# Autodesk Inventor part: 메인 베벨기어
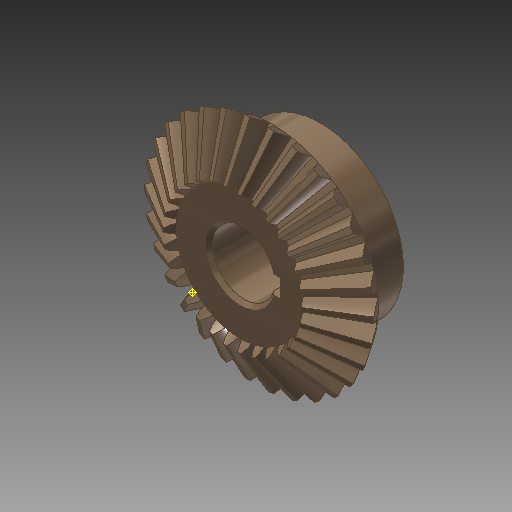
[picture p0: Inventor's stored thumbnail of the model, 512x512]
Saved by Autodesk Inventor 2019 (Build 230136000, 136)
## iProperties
Created: 2014-10
Part Number: 메인 베벨기어
Material: 강철, 탄소
Document SubType Name: Modeling
Designer: KYOUNG IL JANG
Categories: <?xml version="1.0" encoding="UTF-16"?> <MemberInstance><Categories><FamilyTemplate><FamilyTemplateParameter ValueType="xs:double" Id="1" ObjectReferenceKey="da
Mass: 269.926 g
Surface Area: 108.837 cm^2
Volume: 34.2981 cm^3
Density: 7.87 g/cm^3
Appearance: 얼룩무늬
CustomPartVersion: 1
Revision Number: 1
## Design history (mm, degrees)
node "맨 위 점"
node "메쉬 평면2"
sketch "톱니 본체 스케치"
  geometry: L1 (0, 0)-(28.669, -21.997); L2 (28.669, -21.997)-(31.109, -18.336); L3 (31.109, -18.336)-(0, 0); L4 (30, -20)-(0, 0); L5 (17.219, -13.212)-(18.685, -11.013); L6 (28.669, -21.997)-(17.219, -13.212); L7 (31.109, -18.336)-(18.685, -11.013); L8 (0, -39.387)-(0, 6.564) reference; L9 (0, -20)-(31.109, -20)
  constraints: 16 end point, 4 point on line, 3 perpendicular, 2 collinear, 1 horizontal alignment, 1 vertical alignment
  dimensions: "d0" = 60 diameter of L4.start L8 (= da_de); "d1" = 57.33744 diameter of L1.end L8 (= da_dfe); "d2" = 62.2188 diameter of L2.end L8 (= da_dae); "d3" = 14.4 distance between parallel lines of L2 L5 (= da_b); "d4" = 18.3359 vertical distance of L2.end L1.start (= da_ve)
revolve "톱니 본체" sketch "톱니 본체 스케치" stored, may be unused: angle "d5" = 90 deg
node "시작점"
node "톱니 평면"
sketch "시작 스케치"
  geometry: L1 (0, -23.505)-(0, 10.645) reference; L2 (-0.709, -2.928)-(0.709, -2.928); A1 r 19.188 centre (-19.457, -7.014) between (-0.709, -2.928) and (-3.232, 3.229); A2 r 19.188 centre (19.457, -7.014) between (3.232, 3.229) and (0.709, -2.928); A3 r 57.403 centre (0, -54.083) between (3.232, 3.229) and (-3.232, 3.229); 1 further point
  constraints: 6 point on circle, 3 centre point, 3 symmetric about line, 2 end point, 1 coincident, 1 perpendicular, 1 other
  dimensions: "d7" = 19.18795 radius of A1 (= fd_rr); "d8" = 19.45712 horizontal distance of point (0, -54.083) A1.centre (= fd_x); "d9" = 47.06905 vertical distance of point (0, -54.083) A1.centre (= fd_y); "d57" = 57.40327 radius of A3 (= 0.5 x fd_dva + 0.3 x da_he); "d58" = 51.15527 distance from line of A3.centre L2 (= 0.5 x fd_dva - 1.12 x da_he)
node "끝점"
  node "끝 평면"
sketch "3D 스케치 오른쪽"
  node "Helical Curve Right" dims "d65" = 229.90621 (computed from da_dm, da_delta, da_beta), "d66" = 31.5, "d67" = 60 (= da_de), "d68" = -9.82794 (= -da_delta), "d69" = 8.10972 (computed from fd_loft, da_delta)
node "끝 평면 오른쪽"
sketch "끝 스케치 오른쪽"
  geometry: L1 (0, -41.54)-(0, 13.178) reference; L2 (-0.422, -1.69)-(0.422, -1.69); A1 r 11.427 centre (-11.587, -4.123) between (-0.422, -1.69) and (-1.925, 1.977); A2 r 11.427 centre (11.587, -4.123) between (1.925, 1.977) and (0.422, -1.69); A3 r 34.184 centre (0, -32.153) between (1.925, 1.977) and (-1.925, 1.977); 1 further point
  constraints: 6 point on circle, 3 centre point, 3 symmetric about line, 2 end point, 1 coincident, 1 perpendicular, 1 other
  dimensions: "d70" = 11.58699 horizontal distance of A3.centre A1.centre (computed from fd_x, fd_ratio); "d71" = 28.03028 vertical distance of point (0, -32.153) A1.centre (computed from fd_y, fd_ratio); "d72" = 11.4267 radius of A1 (computed from fd_rr, fd_ratio); "d73" = 30.46369 distance from line of point (0, -32.153) L2 (computed from d58, fd_ratio); "d74" = 34.18446 radius of A3 (computed from d57, fd_ratio)
feature "로프트 오른쪽" sketch "끝 스케치 오른쪽" dims "d75" = 0, "d77" = 0, "d79" = 0, "d80" = 90 deg, "d85" = 20, "d92" = 90 deg, "d93" = 90 deg, "da_teethtype" = 0 [user parameter]
sketch "3D 스케치 왼쪽"
  node "Helical Curve Left" dims "d26" = 229.90621 (computed from da_dm, da_delta, da_beta), "d27" = 8.10972 (computed from fd_loft, da_delta), "d28" = 60 (= da_de), "d29" = -9.82794 (= -da_delta)
node "끝 평면 왼쪽"
sketch "끝 스케치 왼쪽" dims "d56" = 10.3728 (derived)
  geometry: L1 (0, -43.753)-(0, 15.405) reference; L2 (-0.422, -1.678)-(0.422, -1.678); A1 r 11.427 centre (-11.587, -4.111) between (-0.422, -1.678) and (-1.925, 1.988); A2 r 11.427 centre (11.587, -4.111) between (1.925, 1.988) and (0.422, -1.678); A3 r 34.184 centre (0, -32.142) between (1.925, 1.988) and (-1.925, 1.988); 2 further points; 1 other entity
  constraints: 6 point on circle, 3 centre point, 3 symmetric about line, 2 end point, 1 coincident, 2 other
  dimensions: "d30" = 11.4267 radius of A1 (computed from fd_rr, fd_ratio); "d31" = 11.58699 horizontal distance of point (0, -32.142) A1.centre (computed from fd_x, fd_ratio); "d32" = 28.03028 vertical distance of A1.centre point (0, -32.142) (computed from fd_y, fd_ratio); "d61" = 34.18446 radius of A3 (computed from d57, fd_ratio); "d62" = 30.46369 distance from line of point (0, -32.142) L2 (computed from d58, fd_ratio)
feature "로프트 왼쪽" sketch "끝 스케치 왼쪽" dims "d35" = 0, "d37" = 0, "d39" = 0, "d40" = 90 deg, "d84" = 10, "d90" = 90 deg, "d91" = 90 deg, "da_teethtype" = 0 [user parameter]
sketch "본체 스케치"
  geometry: L1 (0, -35.038)-(0, -19.531) reference; L2 (28.669, -21.997)-(17.219, -13.212) reference; L3 (17.219, -13.212)-(0, -13.212); L4 (28.669, -21.997)-(0, -21.997)
  constraints: 4 end point, 2 perpendicular, 2 point on line
revolve "본체 고정" sketch "본체 스케치" stored, may be unused: angle "d46" = 90 deg
feature "피치 지름" dims angle "d47" = 90 deg
sketch "스케치8"
  geometry: C1 r 22.5 at (0, 0); 1 further point
  constraints: 1 centre point, 1 coincident
  dimensions: "d94" = 45 diameter of C1
extrude "돌출1" join sketch "스케치8" distance "d95" = 13; taper "d96" = 0 deg
sketch "스케치9"
  geometry: 1 further point
hole "구멍1" sketch "스케치9" at (0, 0) diameter "d97" = 17; stored, may be unused: countersink angle "d101" = 90 deg, drill point angle "d103" = 118 deg; dims "d98" = 6, "d99" = 4, "d100" = 2, "d102" = 8
sketch "스케치10"
  geometry: L1 (8.124, 2.5)-(10.8, 2.5); L2 (10.8, 2.5)-(10.8, -2.5); L3 (10.8, -2.5)-(8.124, -2.5); A1 r 8.5 centre (0, 0) between (8.124, 2.5) and (8.124, -2.5) reference; 1 further point
  constraints: 6 end point, 2 parallel, 2 point on circle, 1 horizontal, 1 perpendicular
  dimensions: "d104" = 5 distance of L1.end L2.end; "d112" = 19.3 dimension on A1 L2
extrude "돌출2" cut sketch "스케치10" extent not by distance; stored distance "d106" = 10; taper "d107" = 0 deg
chamfer "모따기1" distance "d108" = 1; stored, may be unused: second distance "d109" = 2, angle "d110" = 45 deg
fillet "모깎기1" dims "d111" = 2
body "Solid1"
feature "로프트" dims "d17" = 0, "d18" = 90 deg, "d19" = 0, "d20" = 90 deg, "d89" = 0, "da_teethtype" = 0 [user parameter]
pattern_circular "원형 패턴" dims angle "d22" = 360 deg, "d88" = 0, "da_teethtype" = 0 [user parameter]
pattern_circular "원형 패턴 오른쪽" dims angle "d82" = 360 deg, "da_teethtype" = 0 [user parameter]
pattern_circular "원형 패턴 왼쪽" dims angle "d42" = 360 deg, "da_teethtype" = 0 [user parameter]
sketch "끝 스케치"
  geometry: L1 (0, -15.359)-(0, 6.983) reference; L2 (-0.422, -1.69)-(0.422, -1.69); A1 r 11.427 centre (-11.587, -4.123) between (-0.422, -1.69) and (-1.925, 1.977); A2 r 11.427 centre (11.587, -4.123) between (1.925, 1.977) and (0.422, -1.69); A3 r 34.184 centre (0, -32.153) between (1.925, 1.977) and (-1.925, 1.977); 1 further point
  constraints: 6 point on circle, 3 centre point, 3 symmetric about line, 2 end point, 1 coincident, 1 other
  dimensions: "d12" = 11.4267 radius of A1 (computed from fd_rr, fd_ratio); "d15" = 11.58699 horizontal distance of A1.centre point (0, -32.153) (computed from fd_x, fd_ratio); "d16" = 28.03028 vertical distance of A1.centre point (0, -32.153) (computed from fd_y, fd_ratio); "d59" = 34.18446 radius of A3 (computed from d57, fd_ratio); "d60" = 30.46369 distance from line of A3.centre L2 (computed from d58, fd_ratio)
sketch "Sketch6"
  geometry: L1 (30, -20)-(0, 0) reference; L2 (0, -37.8)-(0, 6.3) reference
body "Srf1"
other parameters: "da_b" = 14.4 [user parameter; used in 2 equation terms], "da_de" = 60 [user parameter; used in 4 equation terms], "da_dae" = 62.2188 [user parameter; used in 2 equation terms], "da_dfe" = 57.33744 [user parameter; used in 1 equation term], "da_le" = 36.05551 [user parameter; used in 1 equation term], "da_omega" = 90 deg [user parameter; used in 1 equation term], "da_beta" = 0 [user parameter; used in 2 equation terms], "da_delta" = 9.82794 [user parameter; used in 8 equation terms], "da_alpha" = 20 deg [user parameter; used in 2 equation terms], "da_he" = 4.4 [user parameter; used in 4 equation terms], "da_ve" = 18.3359 [user parameter; used in 1 equation term], "fd_dv" = 108.16654 (computed from da_de, da_delta) [user parameter; used in 1 equation term], "fd_dva" = 112.16654 (computed from da_dae, da_delta) [user parameter; used in 3 equation terms], "fd_dvb" = 101.6433 (computed from fd_dv, da_alpha) [user parameter; used in 2 equation terms], "da_zv" = 540.83269 [user parameter; used in 1 equation term], "fd_loft" = 14.62 (= da_b + 0.05 x da_he) [user parameter; used in 4 equation terms], "fd_ratio" = 5.95514 (computed from da_le, fd_loft) [user parameter; used in 15 equation terms], "fd_rr" = 19.18795 (computed from fd_dd, fd_dvb) [user parameter; used in 6 equation terms], "fd_angle" = 0.29367 (computed from da_zv) [user parameter; used in 4 equation terms], "fd_x1" = 1.58802 (computed from da_dvw, fd_angle) [user parameter; used in 1 equation term], "fd_y1" = 54.05995 (computed from da_dvw, fd_angle) [user parameter; used in 1 equation term], "fd_x2" = 17.8691 (computed from fd_rr, fd_angle2, fd_angle) [user parameter; used in 1 equation term], "fd_y2" = 6.9909 (computed from fd_rr, fd_angle2, fd_angle) [user parameter; used in 1 equation term], "fd_x" = 19.45712 (= fd_x1 + fd_x2) [user parameter; used in 4 equation terms], "fd_y" = 47.06905 (= fd_y1 - fd_y2) [user parameter; used in 4 equation terms], "fd_angle2" = 3.43555 (computed from fd_dvb, fd_dd, da_alpha) [user parameter; used in 2 equation terms], "fd_dd" = 108.64654 (= fd_dva - 0.8 x da_he) [user parameter; used in 2 equation terms], "da_dvw" = 108.16654 [user parameter; used in 2 equation terms], "d11" = 14.62 (= fd_loft), "da_dm" = 48.01848 [user parameter; used in 2 equation terms], "da_x" = 0 [user parameter], "da_m" = 2 [user parameter], "d48" = 0, "d49" = 0, "d50" = 90 deg (= da_omega), "d51" = 6 deg (computed from da_z), "d52" = 0, "d53" = 0, "d54" = 0
